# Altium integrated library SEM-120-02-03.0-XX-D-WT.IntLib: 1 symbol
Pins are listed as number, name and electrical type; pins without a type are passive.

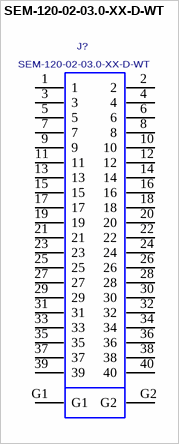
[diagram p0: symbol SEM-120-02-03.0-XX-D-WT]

## SEM-120-02-03.0-XX-D-WT
designator J?
0.8MM TIGER EYE MICRO SOCKET, 40 PINS.; MANUFACTURER: SAMTEC
footprint SEM-120-02-03.0-XX-D-WT
pins: 1, 2, 3, 4, 5, 6, 7, 8, 9, 10, 11, 12, 13, 14, 15, 16, 17, 18, 19, 20, 21, 22, 23, 24, 25, 26, 27, 28, 29, 30, 31, 32, 33, 34, 35, 36, 37, 38, 39, 40, G1, G2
